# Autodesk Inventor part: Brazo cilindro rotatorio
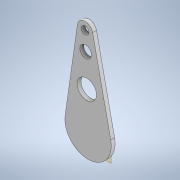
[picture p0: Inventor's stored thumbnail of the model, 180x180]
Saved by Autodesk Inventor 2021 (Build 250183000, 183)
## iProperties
Created: 2021-02
Part Number: Brazo cilindro rotatorio
Material: Genérico
Document SubType Name: Modeling
Designer: ATOUZA
Density: 1 g/cm^3
Appearance: Valor por defecto
Author: ATOUZA
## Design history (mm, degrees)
node "Plano de trabajo1"
sketch "Boceto1"
  geometry: L1 (69.16, 104.528)-(-380.578, 89.171) reference; L2 (68.477, 124.517)-(-381.26, 109.16) reference; L3 (18.307, 122.803)-(18.989, 102.815); L4 (51.827, 6.32)-(28.424, 114.916); L5 (8.751, 114.244)-(-7.19, 4.305); L6 (22.5, 0)-(18.648, 112.809); C1 r 2.5 at (11.186, 11.314) reference; C2 r 12.5 at (20.873, 47.659); C3 r 7.5 at (19.455, 89.171); C4 r 5 at (18.648, 112.809); A1 r 112.875 centre (22.5, 0) between (18.648, 112.809) and (8.679, 112.026); A2 r 30 centre (22.5, 0) between (-7.19, 4.305) and (51.827, 6.32); A3 r 10 centre (18.648, 112.809) between (28.647, 112.707) and (8.679, 112.026); 2 further points
  constraints: 9 point on circle, 8 end point, 6 centre point, 4 point on line, 4 tangent, 3 coincident, 1 horizontal alignment, 1 midpoint
  dimensions: "d0" = 60 diameter of A2; "d1" = 20 diameter of A3; "d2" = 225.75 diameter of A1; "d3" = 25 diameter of C2; "d4" = 15 diameter of C3; "d7" = 10 diameter of C4
extrude "Extrusión1" new body sketch "Boceto1" distance "d5" = 5; taper "d6" = 0 deg
node "Sólido1"
node "Referencia1"
node "Referencia2"
node "Referencia3"
node "Referencia4"
